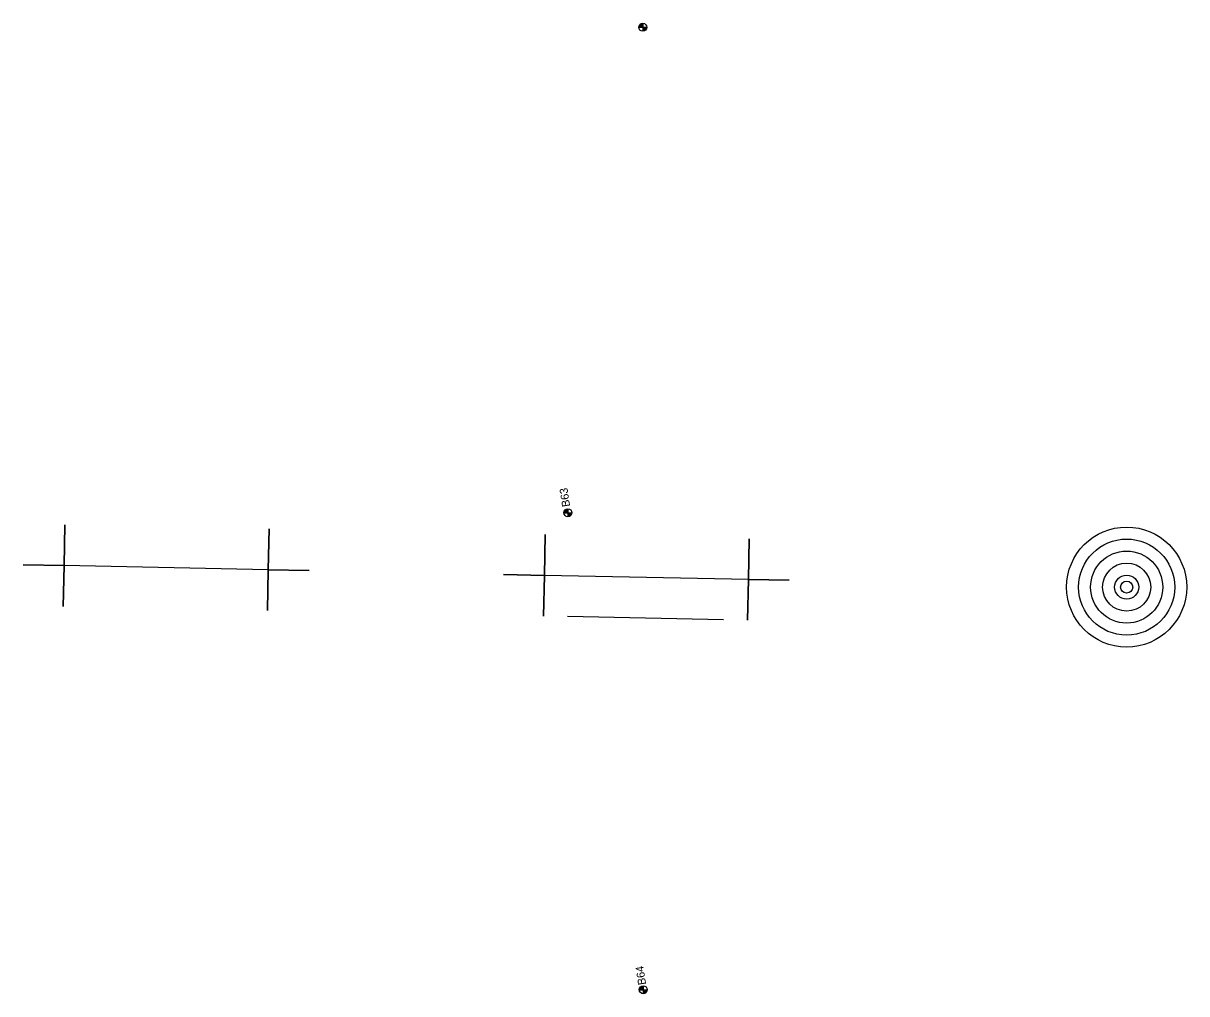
# Model space of a CAD drawing. Extents: x 345549 to 379569, y 127949 to 230467.
# Drawn here: x 358669 to 360122, y 164656 to 165868 of the extents above; entities that cross this region are included whole.
import ezdxf

# ---------------------------------------------------------------- set-up
doc = ezdxf.new("R2010")
doc.units = 0
for name, color, linetype in [('E_SOIL_BORE1 [KAPUR_CADDS_LEVELS]', 7, 'Continuous'), ('P_MARK', 7, 'Continuous'), ('P_TC', 7, 'Continuous')]:
    doc.layers.add(name, color=color, linetype=linetype)

msp = doc.modelspace()

# ---------------------------------------------------------------- linework, layer by layer
at = {"layer": 'P_MARK'}
for p, q in [((359437.8, 165863.3), (359447.8, 165863.3)), ((359442.8, 165868.3), (359442.8, 165858.3)), ((359349.2, 165261.8), (359349.2, 165251.8)), ((359344.2, 165256.8), (359354.2, 165256.8)), ((359443.4, 164665.9), (359443.4, 164655.9)), ((359438.4, 164660.9), (359448.4, 164660.9))]:
    msp.add_line(p, q, dxfattribs=at)
for centre in [(359442.8, 165863.3), (359349.2, 165256.8), (359443.4, 164660.9)]:
    msp.add_circle(centre, 5, dxfattribs=at)
for centre, radius, start, end in [((359442.8, 165863.3), 4.5, 89.9869, 179.9869), ((359442.8, 165863.3), 4, 89.9869, 179.9869), ((359442.8, 165863.3), 3.5, 89.9869, 179.9869), ((359442.8, 165863.3), 3, 89.9869, 179.9869), ((359442.8, 165863.3), 2.5, 89.9869, 179.9869), ((359442.8, 165863.3), 2, 89.9869, 179.9869), ((359442.8, 165863.3), 1.5, 89.9869, 179.9869), ((359442.8, 165863.3), 1, 89.9869, 179.9869), ((359442.8, 165863.3), 0.5, 89.9869, 179.9869), ((359442.8, 165863.3), 4.5, 269.9869, 359.9869), ((359442.8, 165863.3), 4, 269.9869, 359.9869), ((359442.8, 165863.3), 3.5, 269.9869, 359.9869), ((359442.8, 165863.3), 3, 269.9869, 359.9869), ((359442.8, 165863.3), 2.5, 269.9869, 359.9869), ((359442.8, 165863.3), 2, 269.9869, 359.9869), ((359442.8, 165863.3), 1.5, 269.9869, 359.9869), ((359442.8, 165863.3), 1, 269.9869, 359.9869), ((359442.8, 165863.3), 0.5, 269.9869, 359.9869), ((359349.2, 165256.8), 4.5, 89.9869, 179.9869), ((359349.2, 165256.8), 4, 89.9869, 179.9869), ((359349.2, 165256.8), 3.5, 89.9869, 179.9869), ((359349.2, 165256.8), 3, 89.9869, 179.9869), ((359349.2, 165256.8), 2.5, 89.9869, 179.9869), ((359349.2, 165256.8), 2, 89.9869, 179.9869), ((359349.2, 165256.8), 1.5, 89.9869, 179.9869), ((359349.2, 165256.8), 1, 89.9869, 179.9869), ((359349.2, 165256.8), 0.5, 89.9869, 179.9869), ((359349.2, 165256.8), 4.5, 269.9869, 359.9869), ((359349.2, 165256.8), 4, 269.9869, 359.9869), ((359349.2, 165256.8), 3.5, 269.9869, 359.9869), ((359349.2, 165256.8), 3, 269.9869, 359.9869), ((359349.2, 165256.8), 2.5, 269.9869, 359.9869), ((359349.2, 165256.8), 2, 269.9869, 359.9869), ((359349.2, 165256.8), 1.5, 269.9869, 359.9869), ((359349.2, 165256.8), 1, 269.9869, 359.9869), ((359349.2, 165256.8), 0.5, 269.9869, 359.9869), ((359443.4, 164660.9), 4.5, 89.9869, 179.9869), ((359443.4, 164660.9), 4, 89.9869, 179.9869), ((359443.4, 164660.9), 3.5, 89.9869, 179.9869), ((359443.4, 164660.9), 3, 89.9869, 179.9869), ((359443.4, 164660.9), 2.5, 89.9869, 179.9869), ((359443.4, 164660.9), 2, 89.9869, 179.9869), ((359443.4, 164660.9), 1.5, 89.9869, 179.9869), ((359443.4, 164660.9), 1, 89.9869, 179.9869), ((359443.4, 164660.9), 0.5, 89.9869, 179.9869), ((359443.4, 164660.9), 4.5, 269.9869, 359.9869), ((359443.4, 164660.9), 4, 269.9869, 359.9869), ((359443.4, 164660.9), 3.5, 269.9869, 359.9869), ((359443.4, 164660.9), 3, 269.9869, 359.9869), ((359443.4, 164660.9), 2.5, 269.9869, 359.9869), ((359443.4, 164660.9), 2, 269.9869, 359.9869), ((359443.4, 164660.9), 1.5, 269.9869, 359.9869), ((359443.4, 164660.9), 1, 269.9869, 359.9869), ((359443.4, 164660.9), 0.5, 269.9869, 359.9869)]:
    msp.add_arc(centre, radius, start, end, dxfattribs=at)
at = {"layer": 'P_TC'}
for p, q in [((358720, 165190.7), (358721, 165241.7)), ((358721, 165241.7), (358720, 165190.7)), ((358976, 165236.5), (358974.9, 165185.5)), ((358974.9, 165185.5), (358976, 165236.5)), ((359319.9, 165178.6), (359320.9, 165229.6)), ((359320.9, 165229.6), (359319.9, 165178.6)), ((359575.8, 165224.4), (359574.8, 165173.4)), ((359574.8, 165173.4), (359575.8, 165224.4)), ((358720, 165190.7), (358669, 165191.7)), ((358669, 165191.7), (358720, 165190.7)), ((358720, 165190.7), (358719, 165139.7)), ((358719, 165139.7), (358720, 165190.7)), ((358974.9, 165185.5), (358720, 165190.7)), ((358974.9, 165185.5), (358973.9, 165134.5)), ((358973.9, 165134.5), (358974.9, 165185.5)), ((358974.9, 165185.5), (359025.9, 165184.5)), ((359025.9, 165184.5), (358974.9, 165185.5)), ((359319.9, 165178.6), (359268.9, 165179.6)), ((359268.9, 165179.6), (359319.9, 165178.6)), ((359319.9, 165178.6), (359318.8, 165127.6)), ((359318.8, 165127.6), (359319.9, 165178.6)), ((359574.8, 165173.4), (359319.9, 165178.6)), ((359574.8, 165173.4), (359573.8, 165122.5)), ((359573.8, 165122.5), (359574.8, 165173.4)), ((359574.8, 165173.4), (359625.8, 165172.4)), ((359625.8, 165172.4), (359574.8, 165173.4)), ((359543.8, 165123.1), (359348.8, 165127))]:
    msp.add_line(p, q, dxfattribs=at)
for radius in [75, 60, 45, 30, 15, 7.5]:
    msp.add_circle((360047.2, 165163.9), radius, dxfattribs=at)

# ---------------------------------------------------------------- texts
at = {"layer": 'E_SOIL_BORE1 [KAPUR_CADDS_LEVELS]'}
for s, p in [('B63', (359352.1, 165264.9)), ('B64', (359447, 164667.6))]:
    msp.add_text(s, height=10, rotation=98.5151, dxfattribs=at).set_placement(p)

doc.saveas('drawing.dxf')
